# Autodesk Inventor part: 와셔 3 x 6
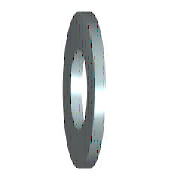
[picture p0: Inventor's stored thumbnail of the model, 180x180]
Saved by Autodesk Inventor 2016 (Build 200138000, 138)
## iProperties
IsCustomPart: 0
Created: 2012-02
Part Number: 와셔 3 x 6
Material: 강철, 연강
Description: 평면 와셔
Document SubType Name: Modeling
Standard: KS B 1326
Designer: mduedu
Standards Organization: KS
Language: ko-KR
Size Designation: 3x6
Categories: <MemberInstance><Categories><Category DisplayName="조임쇠" InternalName="e4da775c-781d-43d5-af7c-5136215cf5a6" Mnemonic="FSTN"><Category DisplayName="와셔" InternalN
Density: 7.86 g/cm^3
Mass: 0.0795112 g
Surface Area: 0.54915 cm^2
Volume: 0.0101159 cm^3
Appearance: 파란색 - 벽 페인트 - 광택
Author: mduedu
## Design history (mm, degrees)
sketch "스케치"
  geometry: C1 r 3 at (0, 0); C2 r 1.6 at (0, 0); 1 further point
  constraints: 2 centre point, 2 coincident
  dimensions: "d0" = 3.2 diameter of C2 (= SD1); "d1" = 6 diameter of C1 (= SD2)
extrude "본체" new body sketch "스케치" distance "d2" = 0.5 (= SD); taper "d3" = 0 deg
workaxis "Work Axis1"
workplane "Work Plane1"
body "Solid1"
other parameters: "SD1" = 3.2 [user parameter; used in 1 equation term], "SD2" = 6 [user parameter; used in 1 equation term], "SD" = 0.5 [user parameter; used in 1 equation term], "d4" = 0, "d5" = 0, "d6" = 0, "d7" = 0, "NND" = 3 [user parameter]
